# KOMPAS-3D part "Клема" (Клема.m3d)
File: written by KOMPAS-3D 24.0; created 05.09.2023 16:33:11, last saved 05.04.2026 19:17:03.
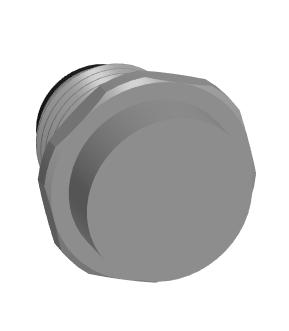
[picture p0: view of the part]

Document properties: Полное имя файла: E:\Работа\Зайцев\Аксессуары для пневмоприводов\Электропневматические позиционеры DN.ru\ЭИП Электропневматический позиционер DN.ru\ЭИП-1500 Электропневматический позиционер DN.ru\3D модели. Позиционер VALMA LPOS-S-V1 (КОМПАС)\Клема.m3d

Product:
- Body: Тело 8  | qty 1
    Масса: 0.013338
- Part/product: Клема
    Масса: 3.501643

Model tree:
1. Операция без истории:8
